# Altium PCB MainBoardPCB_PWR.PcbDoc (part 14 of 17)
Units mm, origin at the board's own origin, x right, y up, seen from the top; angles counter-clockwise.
Board outline 333.63 x 349.38 mm, 16 copper layers (L1, L2 (GND), L3 (Sign), L4 (GND), L5 (Sign), L6 (PWR/GND), L7(PWR/GND), L8 (PWR/GND), L9 (PWR/GND), L10 (PWR/GND), L11 (PWR/GND), L12 (Sign), L13 (GND), L14 (Sign), L15 (GND), L16), stack 2.503 mm thick; 2187 components, 1615 nets, 7987 pads, 1695 vias.
Unrouted connection lines stored in the file: 4757.
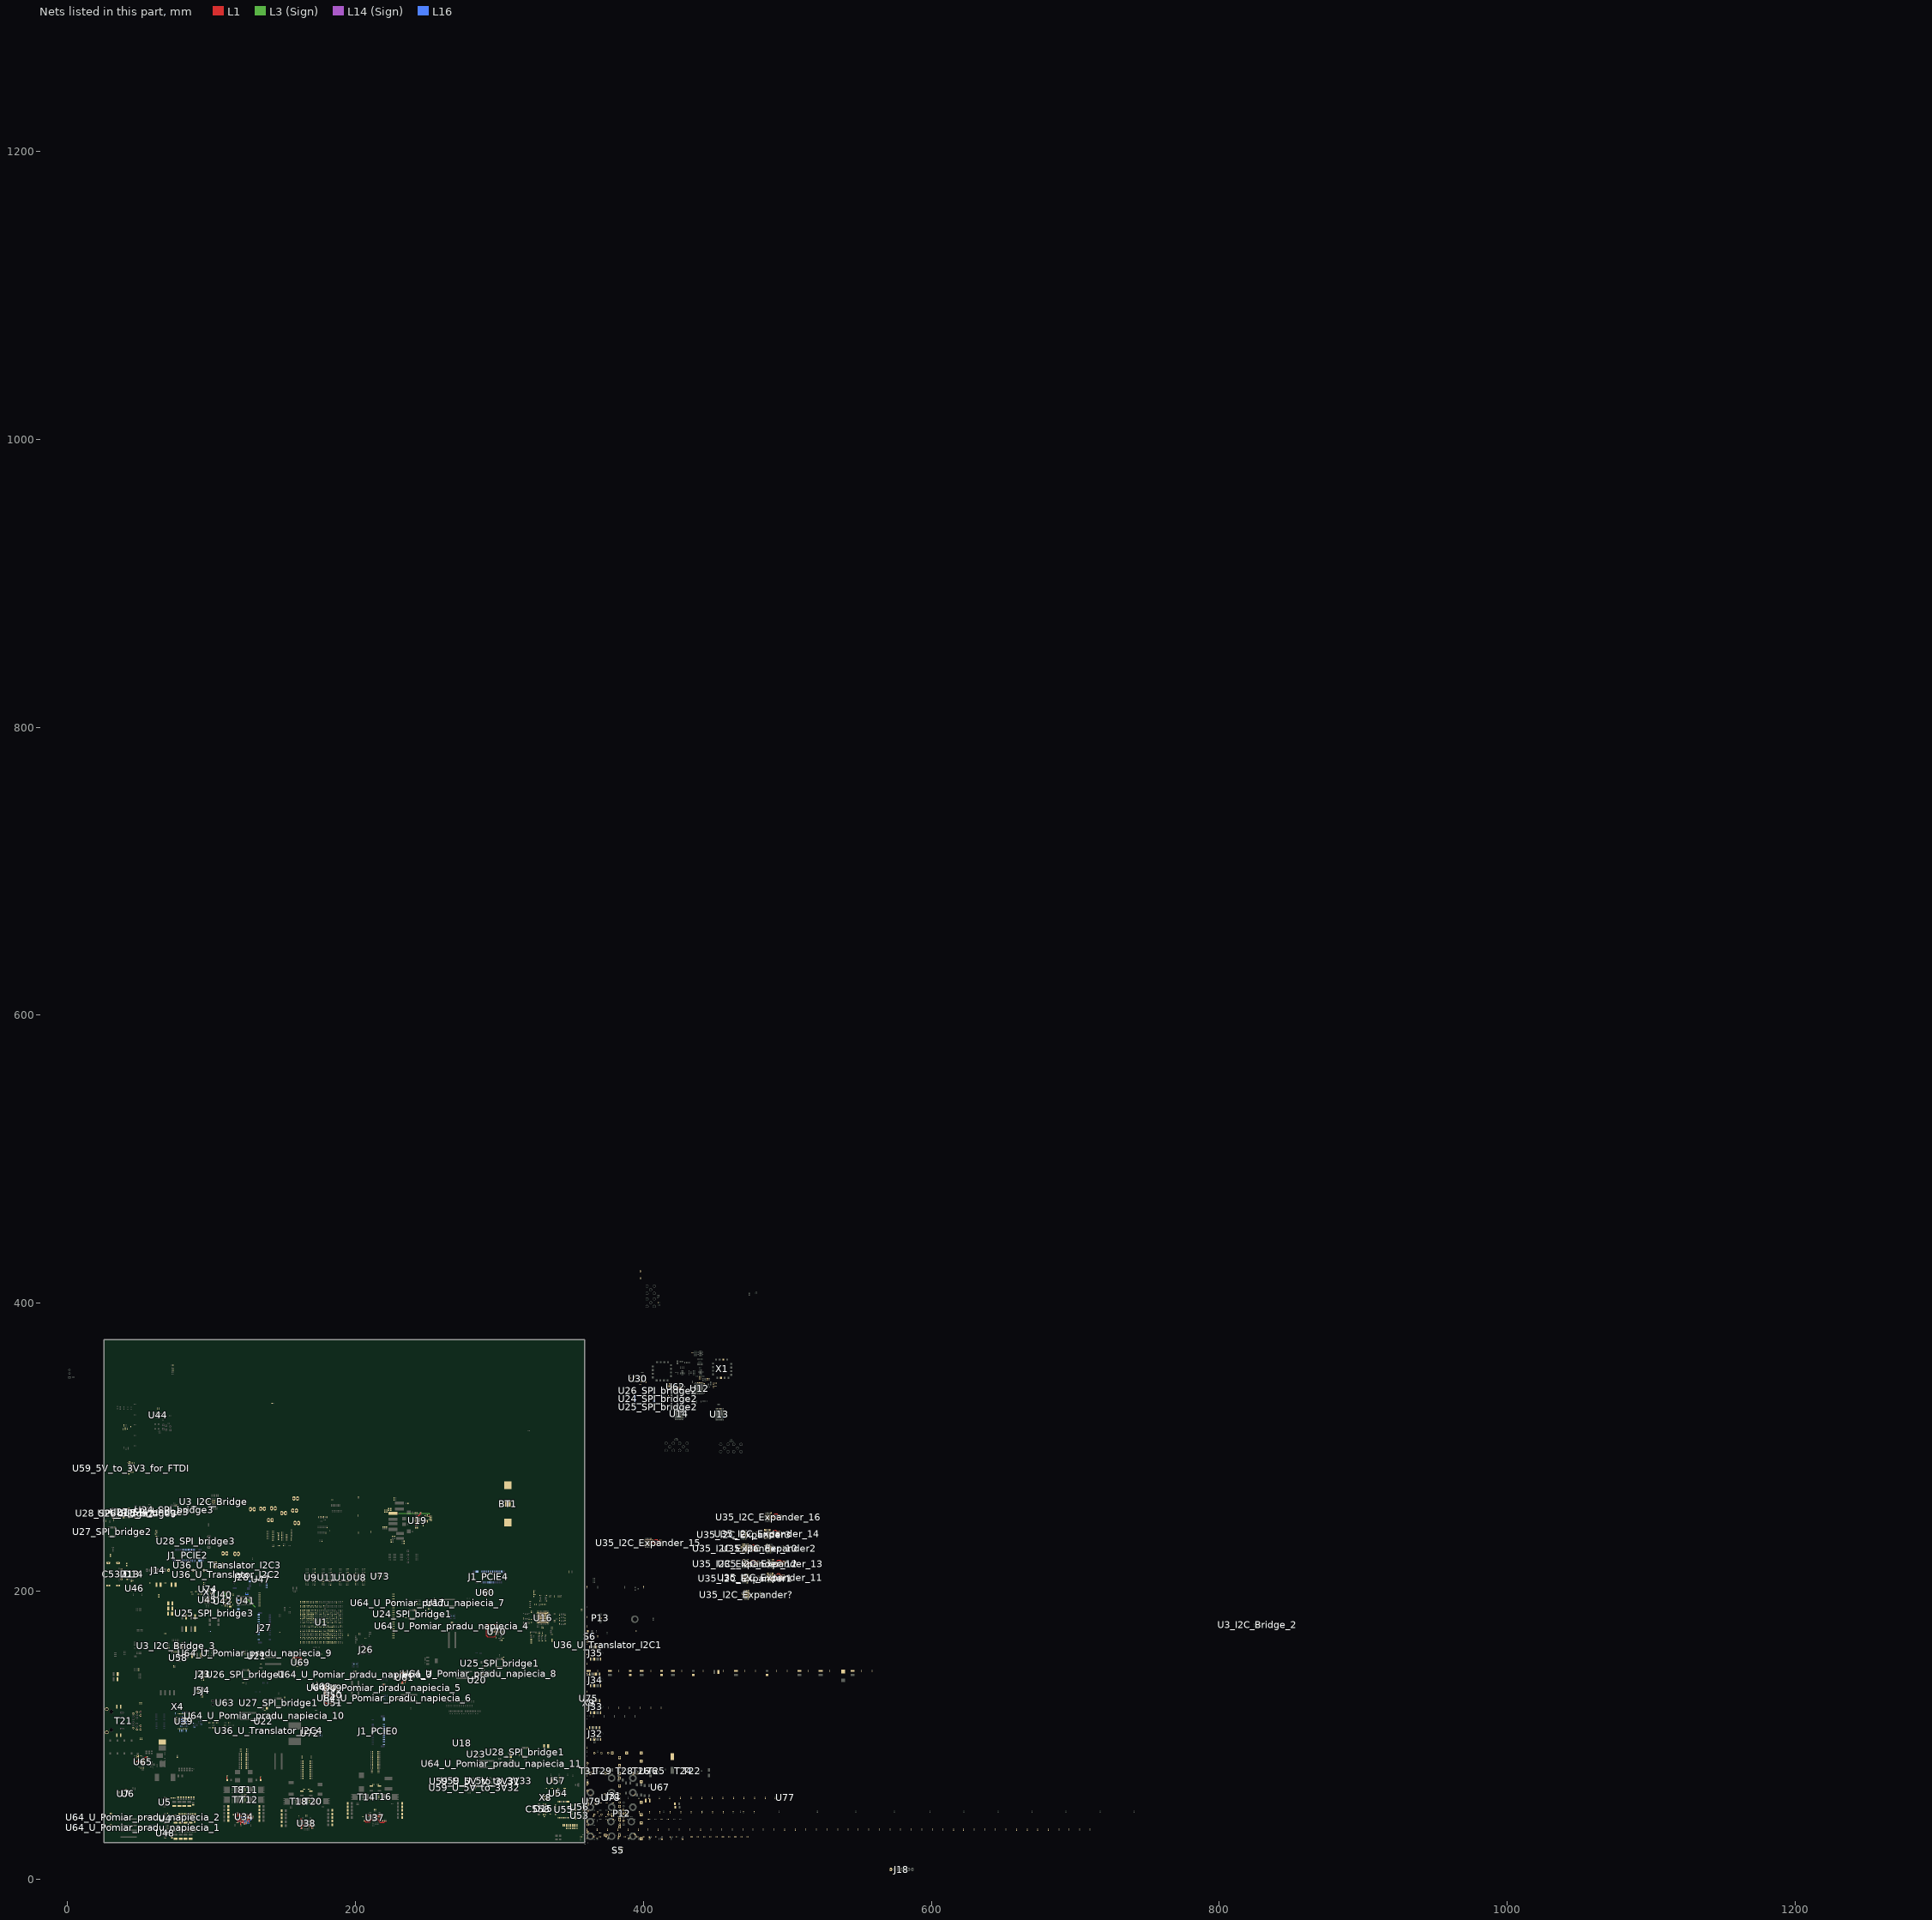
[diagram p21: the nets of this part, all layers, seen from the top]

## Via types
v1: diameter 0.5, hole 0.2, L1 to L16, 786 vias
v2: diameter 0.5/0.35/0.35/0.35/0.35/0.35/0.35/0.35/0.35/0.35/0.35/0.35/0.35/0.35/0.35/0.5 (per signal layer), hole 0.15, L1 to L16, tented both sides, 164 vias
v3: diameter 2.54, hole 1.02, L1 to L16, 152 vias
v4: diameter 0.5/0.35/0.35/0.35/0.35/0.35/0.35/0.35/0.35/0.35/0.35/0.35/0.35/0.35/0.35/0.5 (per signal layer), hole 0.2, L1 to L16, tented both sides, 100 vias
v5: diameter 0.45, hole 0.15, L1 to L16, 79 vias
v6: diameter 0.35/0/0.35 (per signal layer), hole 0.127, L1 to L3 (Sign), tented both sides, 78 vias
v7: diameter 0.45/0.45/0.45/0.45/0.45/0.45/0.45/0.45/0.45/0.45/0.45/0.45/0.45/0.45/0.45/0.45 (per signal layer), hole 0.15, L1 to L16, 65 vias
v8: diameter 0.4, hole 0.15, L1 to L16, 61 vias
v9: diameter 0.2, hole 0.1, L1 to L16, 35 vias
v10: diameter 0.5, hole 0.2, L1 to L16, tented both sides, 32 vias
v11: diameter 0.2/0/0.2 (per signal layer), hole 0.1, L1 to L3 (Sign), 28 vias
v12: diameter 0.4, hole 0.2, L1 to L16, 16 vias
v13: diameter 0.25, hole 0.2, L1 to L16, 16 vias
v14: diameter 0.3, hole 0.2, L1 to L16, 15 vias
v15: diameter 0.5/0.35/0.35/0.35/0.35/0.35/0.35/0.35/0.35/0.35/0.35/0.35/0.35/0.35/0.35/0.45 (per signal layer), hole 0.15, L1 to L16, tented both sides, 10 vias
v16: diameter 5, hole 3, L1 to L16, 9 vias
v17: diameter 0.2/0/0.2 (per signal layer), hole 0.1, L1 to L3 (Sign), tented both sides, 9 vias
v18: diameter 0.35/0/0.35 (per signal layer), hole 0.127, L1 to L3 (Sign), 7 vias
v19: diameter 0.35/0/0.35 (per signal layer), hole 0.127, L14 (Sign) to L16, tented both sides, 5 vias
v20: diameter 1.65, hole 1.65, L1 to L16, 4 vias
v21: diameter 1.15, hole 1.15, L1 to L16, 4 vias
v22: diameter 0.35, hole 0.127, L1 to L2 (GND), 2 vias
v23: diameter 0.4, hole 0.2, L1 to L16, tented both sides, 2 vias
v24: diameter 0.35, hole 0.127, L1 to L2 (GND), tented both sides, 2 vias
v25: diameter 0.508, hole 0.127, L1 to L2 (GND), 2 vias
v26: diameter 0.508, hole 0.127, L2 (GND) to L3 (Sign), 2 vias
v27: diameter 0.35, hole 0.127, L3 (Sign) to L6 (PWR/GND), tented both sides, 2 vias
v28: diameter 0.5, hole 0.2, L3 (Sign) to L6 (PWR/GND), tented both sides, 2 vias
v29: diameter 5.5, hole 3.5, L1 to L16, 1 vias
v30: diameter 0.45/0.45/0.45 (per signal layer), hole 0.15, L1 to L3 (Sign), 1 vias
v31: diameter 0.35/0.35/0.35 (per signal layer), hole 0.127, L1 to L3 (Sign), tented both sides, 1 vias
v32: diameter 0.45/0/0.45 (per signal layer), hole 0.15, L1 to L3 (Sign), tented both sides, 1 vias
v33: diameter 0.45/0/0.45 (per signal layer), hole 0.2, L14 (Sign) to L16, tented both sides, 1 vias
v34: diameter 0.35, hole 0.127, L2 (GND) to L3 (Sign), 1 vias

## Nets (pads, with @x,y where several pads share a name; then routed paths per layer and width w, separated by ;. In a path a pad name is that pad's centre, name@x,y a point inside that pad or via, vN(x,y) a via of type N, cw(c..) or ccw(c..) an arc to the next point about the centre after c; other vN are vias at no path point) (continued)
eMMC_GND: B1.2 BT1.1 C4.2 C5.2 C6.2 C7.2 C8.1 C9.1 C10.1 C11.1 C12.2 C13.2 C14.2 C15.2 C16.1 C17.1 C18.1 C19.1 C20.1 C21.1 C22.1 C23.1 C24.1 C25.1 C26.1 C27.1 C28.1 C29.1 C30.1 C31.1 C32.1 C33.1 C34.1 C35.1 C37.1 C38.2 C39.1 C40.2 C207.1 C208.2 C209.1 C210.2 C211.1 C212.2 C213.1 C214.2 C215.1 C216.2 C217.1 C218.2 C219.2 C220.2 C221.2 C222.2 C223.1 C224.1 C225.1 C226.1 C227.1 C228.1 C229.1 C230.1 C231.1 C232.1 C233.1 C234.1 C235.1 C236.1 C237.1 C238.1 C239.1 C240.1 C241.1 C242.1 C243.2 C244.2 C245.2 C246.2 C247.1 C248.1 C249.1 C250.1 C251.1 C252.1 C253.1 C254.1 C255.1 C256.1 C257.1 C258.1 C259.1 C260.1 C261.1 C262.1 C263.1 C264.1 C265.1 C266.1 C303_I2C_Bridge.1 C303_I2C_Bridge_2.1 C303_I2C_Bridge_3.1 C304.2 C305.2 C306.2 C307.2 C308.1 C309_U_Pomiar_pradu_napiecia_1.1 C309_U_Pomiar_pradu_napiecia_2.1 C309_U_Pomiar_pradu_napiecia_3.1 C309_U_Pomiar_pradu_napiecia_4.1 C309_U_Pomiar_pradu_napiecia_5.1 C309_U_Pomiar_pradu_napiecia_6.1 C309_U_Pomiar_pradu_napiecia_7.1 C309_U_Pomiar_pradu_napiecia_8.1 C309_U_Pomiar_pradu_napiecia_9.1 C309_U_Pomiar_pradu_napiecia_10.1 C309_U_Pomiar_pradu_napiecia_11.1 C310.1 C311_I2C_Expander1.1 C311_I2C_Expander2.1 C311_I2C_Expander3.1 C311_I2C_Expander?.1 C311_I2C_Expander_10.1 C311_I2C_Expander_11.1 C311_I2C_Expander_12.1 C311_I2C_Expander_13.1 C311_I2C_Expander_14.1 C311_I2C_Expander_15.1 C311_I2C_Expander_16.1 C331.1 C332.1 C347.1 C348.1 C352.1 C353.1 C354.1 C355.1 C358.1 C359.1 C360.1 C361.1 C362.1 C363.1 C364.1 C365.1 C366.1 C367.1 C368.1 C369.1 C370.1 C371.1 C372.1 C373.1 C374.1 C375.1 C376.1 C377.1 C378.1 C379.1 C380.1 C381.1 C382.1 C383.1 C384.1 C385.1 C386.1 C387.1 C388.1 C391.2 C392.1 C396.1 C397.2 C399.2 C400.1 C401.1 C402.1 C403.1 C404.1 C405.1 C406.1 C407.1 C408.1 C409.1 C410.1 C411.1 C412.1 C413.1 C414.1 C415.1 C416.1 C417.1 C418.1 C419.1 C420.1 C421.1 C422.1 C423.1 C424.1 C425.1 C426.1 C427.1 C428.1 C429.1 C432.2 C433.1 C437.1 C438.2 C440.2 C441.1 C442.1 C443.1 C444.1 C445.1 C446.1 C447.1 C448.1 C449.1 C450.1 C451.1 C452.1 C453.1 C454.1 C455.1 C456.1 C457.1 C458.1 C459.1 C460.1 C461.1 C462.1 C463.1 C464.1 C465.1 C466.1 C467.1 C468.1 C469.1 C470.1 C471.1 C472.1 C473.1 C474.1 C475.1 C476.1 C480.1 C481.1 C485.1 C486.1 C487.1 C488.1 C489.1 C490.1 C491.1 C492.1 C493.1 C494.1 C495.1 C496.1 C497.1 C498.1 C499.1 C500.1 C501.1 C502.1 C503.1 C504.1 C505.1 C506.1 C507.1 C508.1 C509.1 C510.1 C511.1 C512.1 C513.1 C514.1 C515.1 C516.1 C517.1 C518.1 C519.1 C520.1 C521.1 C522.1 C523.1 C524.1 C537.7 C538.1 C539.1 C544.1 C545.1 C546.1 C547.1 C550.1 C551.1 C552.1 C553.1 C554.1 C555.1 C561.1 C562.1 C585.1 C586.1 C587.1 C606.1 C607.1 C609.1 C610.1 C611.1 C613.1 C614.1 C615.1 C617.1 C618.1 C619.1 C620.1 C621.1 C622.1 C623.1 C624.1 C625.1 C626.1 C631.1 C632.1 C633.1 C636.1 C637.1 C638.1 C645.1 C646.1 C654.1 C655.2 C656.2 C657.2 C672.1 C674.1 C675.1 C676.1 C678.1 C679.1 C680.1 C705.1 C707.1 C708.1 C709.1 C711.1 C712.1 C719.1 C720.1 C721.1 C722.1 C723.1 C728.1 C729.1 C730.1 C731.1 C732.1 C733.1 C734.1 C735.1 C736.1 C737.1 C738.2 C739.2 C740.1 C741.1 C742.2 C743.1 C744.1 C745.1 C746.1 C747.2 C748.1 C749.1 C750.1 C751.2 C752.1 C753.2 C754.1 C755.1 C756.1 C757.2 C758.1 C759.1 C760.2 C761.1 C762.2 C763.1 C764.2 C765.1 C766.2 C767.2 C768.2 C769.2 C770.1 C771.1 C772.1 C773.1 C774.1 C775.1 C776.1 C777.1 C778.1 C779.1 C780.1 C781.1 C782.1 C783.1 C784.1 C785.1 C786.1 C787.1 C788.1 C789.1 C792.1 D13.3 D14.3 D14.8 D15.3 FB27.1 FB28.2 FB29.1 FB35.1 FB36.1 FB39.1 FB41.1 J14.1 J15.1 J16.1 J17.1 J18.1 J19.1 J20.1 J21.1 J22.1 J23.1 J24.1 J27.1 J27.3 J27.9 J27.15 J27.21 J27.27 J27.33 J27.39 J27.45 J27.51 J27.57 J27.63 J27.65 J27.67 J28.6 J31.SH1 J31.SH2 J31.SH3 J31.SH4 J31.SH5 J31.SH6 J31.SH7 J31.SH8 J31.SH9 J31.SH10 J31.SH11 J31.SH12 J31.SH13 J31.SH14 J31.SH15 J31.SH16 J31.SH17 J31.SH18 J31.SH19 J31.SH20 J31.SH21 J31.SH22 J31.SH23 J31.SH24 J31.SH25 J31.SH26 J31.SH27 J31.SH28 J31.SH29 J31.SH30 J31.SH31 J31.SH32 J31.SH33 J31.SH34 J31.SH35 J31.SH36 J31.SH37 J31.SH38 J31.SH39 J31.SH40 J31.SH41 J31.SH42 J31.SH43 J31.SH44 J31.SH45 J31.SH46 J32.1 J32.10 J32.11 J32.14 J32.17 J32.20 J33.1 J33.10 J33.11 J33.14 J33.16 J34.1 J34.10 J34.11 J34.14 J34.16 J35.1 J35.10 J35.11 J35.14 J35.16 P7.1 P9.1 P11.2 P12.2 P12.4 P12.6 P12.8 P12.10 P12.12 P12.14 R2.1 R14.1 R18.1 R19.1 R21.1 R23.1 R25.1 R26.1 R27.1 R28.1 R56.2 R60.2 R61.2 R62.2 R63.2 R64.2 R73.1 R74.1 R109.1 R114.1 R129.2 R139.1 R167.2 R168.2 R170.2 R172.2 R173.2 R174.1 R178.1 R182.1 R183.1 R187.1 R191.1 R192.1 R196.1 R200.1 R201.1 R205.1 R209.1 R210.1 R214.1 R217.1 R218.1 R228.1 R229.1 R242.2 R244.2 R267.1 R269.1 R274.1 R275.1 R279.2 R280.1 R282.2 R284.1 R292.1 R299.1 R304.1 R317.1 R325.1 R326.1 R327.1 R328.1 R334.2 R341.1 R344.1 R345.1 R379.1 R380.1 R393.1 R396.1 R399.1 R400.2 R450.2 R452.2 R454.2 R456.2 R460.2 R461.1 R464.2 R467.1 R470.2 R472.2 R474.2 R476.2 R478.2 R480.2 R493.2 R495.2 R497.2 R501.2 R503.2 R505.2 R509.2 R511.2 R513.2 R517.2 R519.2 R521.2 R525.2 R527.2 R529.2 R561.1 R565.1 R569.1 R573.1 R577.1 R581.1 R585.1 R589.1 R595.1 R601.1 R629.1 R645.1 R652.1 R668.1 R672.1 R674.1 R675.1 R681.1 R682.1 R683.1 R684.1 R685.1 R690.1 R693.2 R696.2 R698.2 R700.2 R702.2 R704.2 R706.2 R708.2 R714.1 R739.2 R741.2 R743.2 R759.2 R761.2 R763.2 R764.1 R838.2 R840.2 R841.2 S6.1 S6.2 T7.1 T7.2 T7.3 T8.1 T8.2 T8.3 T11.1 T11.2 T11.3 T12.1 T12.2 T12.3 T14.1 T14.2 T14.3 T16.1 T16.2 T16.3 T18.1 T18.2 T18.3 T20.1 T20.2 T20.3 T24.2 T25.2 T26.2 T28.2 T29.2 T31.2 U1.A1 U1.A2 U1.A5 U1.A9 U1.A11 U1.A30 U1.AA9 U1.AA19 U1.AA29 U1.AB2 U1.AB7 U1.AB12 U1.AB17 U1.AB22 U1.AC5 U1.AC10 U1.AC20 U1.AD13 U1.AD18 U1.AD23 U1.AE6 U1.AE16 U1.AE21 U1.AF4 U1.AF9 U1.AF19 U1.AF24 U1.AF29 U1.AG2 U1.AG12 U1.AG22 U1.AH5 U1.AH15 U1.AH20 U1.AH25 U1.AJ3 U1.AJ8 U1.AJ13 U1.AJ18 U1.AJ23 U1.AJ28 U1.AK1 U1.AK30 U1.B3 U1.B4 U1.B7 U1.B11 U1.B13 U1.B17 U1.C1 U1.C2 U1.C5 U1.C9 U1.C11 U1.C15 U1.C20 U1.C25 U1.C30 U1.D3 U1.D4 U1.D7 U1.D11 U1.E1 U1.E2 U1.E5 U1.E9 U1.E11 U1.F3 U1.F4 U1.F7 U1.F11 U1.F14 U1.F24 U1.F25 U1.F26 U1.F27 U1.F28 U1.F29 U1.F30 U1.G1 U1.G2 U1.G5 U1.G9 U1.G11 U1.G17 U1.G22 U1.G23 U1.G24 U1.G27 U1.G28 U1.H3 U1.H4 U1.H7 U1.H11 U1.H20 U1.H22 U1.H26 U1.H29 U1.H30 U1.J1 U1.J2 U1.J5 U1.J9 U1.J10 U1.J11 U1.J13 U1.J22 U1.J24 U1.J27 U1.J28 U1.K3 U1.K4 U1.K9 U1.K22 U1.K26 U1.K29 U1.K30 U1.L1 U1.L2 U1.L5 U1.L9 U1.L12 U1.L16 U1.L18 U1.L22 U1.L24 U1.L28 U1.M3 U1.M4 U1.M7 U1.M9 U1.M11 U1.M13 U1.M15 U1.M17 U1.M22 U1.M26 U1.M29 U1.M30 U1.N1 U1.N2 U1.N5 U1.N9 U1.N12 U1.N14 U1.N16 U1.N23 U1.N24 U1.N25 U1.N26 U1.N27 U1.N28 U1.N29 U1.N30 U1.P3 U1.P4 U1.P7 U1.P9 U1.P11 U1.P13 U1.P15 U1.P17 U1.R1 U1.R2 U1.R5 U1.R9 U1.R12 U1.R16 U1.R21 U1.R26 U1.T3 U1.T4 U1.T7 U1.T8 U1.T11 U1.T13 U1.T17 U1.T19 U1.T24 U1.T29 U1.U1 U1.U2 U1.U5 U1.U7 U1.U12 U1.U16 U1.U22 U1.U27 U1.V3 U1.V4 U1.V7 U1.V9 U1.V11 U1.V13 U1.V20 U1.V25 U1.W1 U1.W2 U1.W5 U1.W6 U1.W12 U1.W14 U1.W16 U1.W18 U1.W23 U1.W28 U1.Y2 U1.Y3 U1.Y4 U1.Y5 U1.Y11 U1.Y13 U1.Y15 U1.Y21 U1.Y26 U3_I2C_Bridge.9 U3_I2C_Bridge.25 U3_I2C_Bridge_2.9 U3_I2C_Bridge_2.25 U3_I2C_Bridge_3.9 U3_I2C_Bridge_3.25 U4.3 U4.6 U4.12 U5.3 U5.6 U5.12 U6.A1 U6.A4 U6.B1 U6.B2 U6.B3 U6.B4 U6.C4 U7.A1 U7.A4 U7.B1 U7.B2 U7.B3 U7.B4 U7.C4 U8.A2 U8.A5 U8.B2 U8.C6 U8.D2 U8.D5 U8.E1 U8.E3 U8.E5 U8.E6 U8.F1 U8.G5 U8.H1 U8.H6 U8.K1 U8.K6 U8.M6 U8.N1 U8.T1 U9.A2 U9.A5 U9.B2 U9.C6 U9.D2 U9.D5 U9.E1 U9.E3 U9.E5 U9.E6 U9.F1 U9.G5 U9.H1 U9.H6 U9.K1 U9.K6 U9.M6 U9.N1 U9.T1 U10.A2 U10.A5 U10.B2 U10.C6 U10.D2 U10.D5 U10.E1 U10.E3 U10.E5 U10.E6 U10.F1 U10.G5 U10.H1 U10.H6 U10.K1 U10.K6 U10.M6 U10.N1 U10.T1 U11.A2 U11.A5 U11.B2 U11.C6 U11.D2 U11.D5 U11.E1 U11.E3 U11.E5 U11.E6 U11.F1 U11.G5 U11.H1 U11.H6 U11.K1 U11.K6 U11.M6 U11.N1 U11.T1 U15.2 U15.10 U17.A1 U17.A4 U17.B1 U17.B2 U17.B3 U17.B4 U17.C4 U18.A1 U18.A4 U18.B1 U18.B2 U18.B3 U18.B4 U18.C4 U19.10 U19.18 U19.27 U19.29 U20.A1 U20.A4 U20.B1 U20.B2 U20.B3 U20.B4 U20.C4 U21.A1 U21.A4 U21.B1 U21.B2 U21.B3 U21.B4 U21.C4 U22.A1 U22.A4 U22.B1 U22.B2 U22.B3 U22.B4 U22.C4 U23.A1 U23.A4 U23.B1 U23.B2 U23.B3 U23.B4 U23.C4 U24_SPI_bridge1.2 U24_SPI_bridge1.10 U24_SPI_bridge2.2 U24_SPI_bridge2.10 U24_SPI_bridge3.2 U24_SPI_bridge3.10 U25_SPI_bridge1.2 U25_SPI_bridge1.10 U25_SPI_bridge2.2 U25_SPI_bridge2.10 U25_SPI_bridge3.2 U25_SPI_bridge3.10 U26_SPI_bridge1.2 U26_SPI_bridge1.10 U26_SPI_bridge2.2 U26_SPI_bridge2.10 U26_SPI_bridge3.2 U26_SPI_bridge3.10 U27_SPI_bridge1.2 U27_SPI_bridge1.10 U27_SPI_bridge2.2 U27_SPI_bridge2.10 U27_SPI_bridge3.2 U27_SPI_bridge3.10 U28_SPI_bridge1.2 U28_SPI_bridge1.10 U28_SPI_bridge2.2 U28_SPI_bridge2.10 U28_SPI_bridge3.2 U28_SPI_bridge3.10 U34.19 U34.22 U35_I2C_Expander1.6 U35_I2C_Expander1.29 U35_I2C_Expander2.6 U35_I2C_Expander2.29 U35_I2C_Expander3.6 U35_I2C_Expander3.29 U35_I2C_Expander?.6 U35_I2C_Expander?.29 U35_I2C_Expander_10.6 U35_I2C_Expander_10.29 U35_I2C_Expander_11.6 U35_I2C_Expander_11.29 U35_I2C_Expander_12.6 U35_I2C_Expander_12.29 U35_I2C_Expander_13.6 U35_I2C_Expander_13.29 U35_I2C_Expander_14.6 U35_I2C_Expander_14.29 U35_I2C_Expander_15.6 U35_I2C_Expander_15.29 U35_I2C_Expander_16.6 U35_I2C_Expander_16.29 U36_U_Translator_I2C1.1 U36_U_Translator_I2C2.1 U36_U_Translator_I2C3.1 U36_U_Translator_I2C4.1 U37.19 U37.22 U38.19 U38.22 U39.49 U40.4 U40.9 U41.A6 U41.C4 U41.E7 U41.G5 U41.H10 U41.J5 U41.K8 U41.N2 U41.N5 U41.P4 U41.P6 U42.4 U42.9 U45.23 U45.33 U46.A1 U46.A4 U46.B1 U46.B2 U46.B4 U47.C3 U48.12 U49.4 U49.9 U50.4 U50.9 U51.4 U51.9 U58.2 U58.3 U58.6 U58.7 U63.2 U63.8 U64_U_Pomiar_pradu_napiecia_1.7 U64_U_Pomiar_pradu_napiecia_2.7 U64_U_Pomiar_pradu_napiecia_3.7 U64_U_Pomiar_pradu_napiecia_4.7 U64_U_Pomiar_pradu_napiecia_5.7 U64_U_Pomiar_pradu_napiecia_6.7 U64_U_Pomiar_pradu_napiecia_7.7 U64_U_Pomiar_pradu_napiecia_8.7 U64_U_Pomiar_pradu_napiecia_9.7 U64_U_Pomiar_pradu_napiecia_10.7 U64_U_Pomiar_pradu_napiecia_11.7 U67.2 U68.2 U69.6 U69.17 U70.3 U70.8 U70.13 U70.18 U70.21 U72.7 U73.4 U73.9 U74.3 U75.3 U78.2 X4.2 X4.4 X7.2 X7.4 | length 5.7
  L1 w0.254: U1.AF24@186.927,186.927 v24(186.931,186.923) ; v24(187.924,184.927) U1.AG22@187.927,184.927 ; v22(242.224,246.141) U19.10@242.224,246.658 ; U19.27@242.224,251.458 v18(242.224,252.049) ; v8(295.595,171.723) U70.3@296.284,171.723 v1(297.359,171.723) v1(298.259,171.723)
  L16 w0.254: R577.1@219.302,140.072 R581.1@221.208,140.072
  other v1: 80.087,107.674 81.457,107.674 78.972,108.789 80.087,108.789 81.457,108.789 82.572,108.789 78.972,110.159 80.087,110.159 81.457,110.159 82.572,110.159 80.087,111.274 81.457,111.274 183.759,122.038 184.759,122.038 183.759,123.038 184.759,123.038 183.759,127.285 184.759,127.285 183.759,128.285 184.759,128.285 183.759,132.134 184.759,132.134 183.759,133.134 184.759,133.134 161.168,149.912 162.268,149.912 161.168,151.012 162.268,151.012 297.359,170.823 298.259,170.823 299.159,170.823 299.159,171.723 297.359,172.623 298.259,172.623 299.159,172.623 107.317,192.548 108.317,192.548 107.317,193.548 108.317,193.548 107.316,196.835 108.316,196.835 107.316,197.835 108.316,197.835 469.236,207.067 470.336,207.067 471.436,207.067 472.536,207.067 469.236,208.167 470.336,208.167 471.436,208.167 472.536,208.167 469.236,209.267 470.336,209.267 471.436,209.267 472.536,209.267 216.651,209.883 217.651,209.883 469.236,210.367 470.336,210.367 471.436,210.367 472.536,210.367 216.651,210.883 217.651,210.883 469.12,217.4 470.22,217.4 471.32,217.4 472.42,217.4 469.12,218.5 470.22,218.5 471.32,218.5 472.42,218.5 469.12,219.6 470.22,219.6 471.32,219.6 472.42,219.6 469.12,220.7 470.22,220.7 471.32,220.7 472.42,220.7 485.515,227.915 486.615,227.915 487.715,227.915 488.815,227.915 485.515,229.015 486.615,229.015 487.715,229.015 488.815,229.015 485.515,230.115 486.615,230.115 487.715,230.115 488.815,230.115 485.515,231.215 486.615,231.215 487.715,231.215 488.815,231.215 401.804,231.87 402.904,231.87 404.004,231.87 405.104,231.87 401.804,232.97 402.904,232.97 404.004,232.97 405.104,232.97 401.804,234.07 402.904,234.07 404.004,234.07 405.104,234.07 401.804,235.17 402.904,235.17 404.004,235.17 405.104,235.17 468.195,237.62 469.295,237.62 470.395,237.62 471.495,237.62 468.195,238.72 469.295,238.72 470.395,238.72 471.495,238.72 468.195,239.82 469.295,239.82 470.395,239.82 471.495,239.82 468.195,240.92 469.295,240.92 470.395,240.92 471.495,240.92 242.424,247.958 243.524,247.958 242.424,249.058 243.524,249.058 485.203,249.839 486.303,249.839 487.403,249.839 488.503,249.839 242.424,250.158 243.524,250.158 485.203,250.939 486.303,250.939 487.403,250.939 488.503,250.939 485.203,252.039 486.303,252.039 487.403,252.039 488.503,252.039 485.203,253.139 486.303,253.139 487.403,253.139 488.503,253.139
  other v4: 220.255,140.072 181.927,191.927
  other v5: 66.285,34.081 69.809,35.032 66.285,36.958 69.753,37.017 67.96,38.575 67.56,45.343 67.854,50.161 69.587,56.524 67.512,56.624 292.356,170.033 294.076,170.033
  other v10: 178.927,187.927 180.927,188.927 179.927,190.927
  other v13: 95.498,192.272 96.518,192.272 97.538,192.272 98.558,192.272 95.498,193.292 96.518,193.292 97.538,193.292 98.558,193.292 95.498,194.312 96.518,194.312 97.538,194.312 98.558,194.312 95.498,195.332 96.518,195.332 97.538,195.332 98.558,195.332
  other v14: 75.299,161.107 74.454,161.955 75.299,161.955 76.124,161.955 75.299,162.805 826.389,175.733 825.544,176.581 826.389,176.581 827.214,176.581 826.389,177.431 101.6,261.154 100.755,262.001 101.6,262.001 102.425,262.001 101.6,262.851
eMMC_PG1: R340.1 U40.5 | length 3.6
  L1 w0.164: U40.5@109.116,196.323 U40.5@109.116,196.36 ; v18(109.726,199.669) R340.1@109.776,199.669
  L3 (Sign) w0.164: v18(109.416,196.36) 109.452,196.396 109.665,196.396 109.726,196.456 v18(109.726,199.669)
eMMC_PG2: R343.1 R345.2 U42.5 | length 3.1
  L1 w0.164: U42.5@109.117,192.073 109.242,192.073 109.335,191.98 109.335,191.855 109.572,191.618 R345.2@109.572,190.652 ; R345.2@109.572,190.636 R345.2@109.572,190.652 ; R343.1@110.957,190.652 R345.2@109.572,190.652
eMMC_rst: R99.1 R797.1 U41.K5 | length 10.4
  L1 w0.254: U41.K5@122.468,194.479 v17(122.479,194.479)
  L3 (Sign) w0.098: v17(122.479,194.479) 122.729,194.729 124.47,194.729 130.169,189.031 130.362,189.031
eMMC_Vcc: C517.2 C518.2 C523.2 C586.2 FB25.1 R339.2 R340.2 U40.8 U41.E6 U41.F5 U41.J10 U41.K9
  other v1: 118.164,196.899 119.264,196.899
eMMC_VccQ: C519.2 C520.2 C524.2 C587.2 FB25.2 R342.2 R343.2 U41.C6 U41.M4 U41.N4 U41.P3 U41.P5 U42.8
  other v1: 111.29,188.882 118.249,190.694 119.22,190.694 111.357,193.452 111.357,194.212
eMMC_Vddim: C521.2 C522.2 U41.C2 | length 1.6
  L16 w0.164: C522.2@123.76,197.623 C521.2@125.318,197.623
EN1: U35_I2C_Expander2.23 U61.20
EN1_TPS: R277.2 R278.2 U34.14 U34.27 U70.20 | length 8.3
  L1 w0.254: R278.2@116.439,43.474 116.439,43.524 116.612,43.697 117.019,43.697 117.228,43.906 U34.27@120.477,43.906 ; U34.14@124.977,43.906 124.979,43.904 125.128,43.904 125.132,43.899 126.383,43.899 126.903,43.379 128.704,43.379 R277.2@128.799,43.474
EN2: U35_I2C_Expander2.24 U61.6
EN2_TPS: R745.1 U70.6 U70.17 | length 25
  L1 w0.254: U70.6@297.259,169.748 297.259,168.891 296.591,168.223 291.986,168.223 291.068,169.141 291.068,175.325 292.548,176.805 R745.1@298.259,176.805 298.409,176.655 298.409,176.07 298.399,176.06 298.399,174.709 298.759,174.349 U70.17@298.759,173.698
EN_0.85V_REG1: S5.8 U34.1 U34.8
En_0V85@2A: R296.2 R435.2 U37.14 | length 1.3
  L1 w0.254: U37.14@215.795,43.359 R296.2@217.105,43.359
EN_1V0@1.5A: R634.1 U51.3 U68.4 | length 14.8
  L1 w0.254: U68.4@178.016,132.909 178.266,132.909 178.743,132.432 178.743,123.104 179.628,122.219 R634.1@180.597,122.219 180.6,122.216 182.956,122.216 U51.3@182.959,122.213
EN_1V8@1.5A: R633.1 U50.3 U68.5 | length 10.9
  L1 w0.254: U68.5@178.016,133.859 179.114,133.859 179.263,133.711 179.263,128.084 179.887,127.46 180.564,127.46 R633.1@180.597,127.428 180.613,127.444 182.943,127.444 U50.3@182.959,127.46
EN_2V5@1.5A: R632.1 U49.3 U68.6 | length 6.8
  L1 w0.254: U68.6@178.016,134.809 179.003,134.809 179.803,134.009 179.803,132.644 180.069,132.378 180.424,132.378 R632.1@180.547,132.255 180.601,132.309 U49.3@182.959,132.309
EN_3V3V_REG0: S5.6 U37.1
EN_5V_REG0: S5.7 U38.8
EN_12@8A: S5.5 U38.1
EN_Detect_KEY: R655.2
En_PCIE_I2C: U35_I2C_Expander_14.21
En_PCIE_SPI: U35_I2C_Expander_14.20
EN_PS_LTC6952_1: U35_I2C_Expander2.20 U59_U_5V_to_3V33.3
EN_PS_LTC6952_2: U35_I2C_Expander2.22 U59_U_5V_to_3V32.3
EN_PS_LTC6952_3: U35_I2C_Expander2.17 U59_U_5V_to_3V31.3
En_PWRSwitch_PCIE0: U17.A2 U35_I2C_Expander_14.2
En_PWRSwitch_PCIE1: U20.A2 U35_I2C_Expander_14.18
En_PWRSwitch_PCIE2: U21.A2 U35_I2C_Expander_14.3
En_PWRSwitch_PCIE3: U22.A2 U35_I2C_Expander_14.22
En_PWRSwitch_PCIE4: U23.A2 U35_I2C_Expander_14.19
  other v1: 484.417,237.997 485.517,237.997 486.617,237.997 487.717,237.997 484.417,239.097 485.517,239.097 486.617,239.097 487.717,239.097 484.417,240.197 485.517,240.197 486.617,240.197 487.717,240.197 484.417,241.297 485.517,241.297 486.617,241.297 487.717,241.297
EN_SEQ_LT3504: R646.2 U67.3 U69.5 | length 8.3
  L1 w0.254: R646.2@156.588,153.062 156.588,153.809 156.781,154.002 161.918,154.002 162.693,153.227 U69.5@162.693,152.137
EN_SPI_A_Q0: R232_SPI_bridge3.1 U35_I2C_Expander_10.21
EN_SPI_A_Q1: R234_SPI_bridge3.1 U35_I2C_Expander_10.20
EN_SPI_A_Q2: R235_SPI_bridge3.2 U35_I2C_Expander_10.2
EN_SPI_A_Q3: R237_SPI_bridge3.2 U35_I2C_Expander_10.18
EN_SPI_A_Q4: R239_SPI_bridge3.1 U35_I2C_Expander_10.3
EN_SPI_B_Q0: R232_SPI_bridge1.1 U35_I2C_Expander_10.22 U35_I2C_Expander_15.1
EN_SPI_B_Q1: R234_SPI_bridge1.1 U35_I2C_Expander_10.19 U35_I2C_Expander_15.28
EN_SPI_B_Q2: R235_SPI_bridge1.2 U35_I2C_Expander_10.17 U35_I2C_Expander_15.25
EN_SPI_B_Q3: R237_SPI_bridge1.2 U35_I2C_Expander_10.4 U35_I2C_Expander_15.26
EN_SPI_B_Q4: R239_SPI_bridge1.1 U35_I2C_Expander_10.23 U35_I2C_Expander_15.27
EN_SPI_C_Q0: R232_SPI_bridge2.1 U35_I2C_Expander_10.24
EN_SPI_C_Q1: R234_SPI_bridge2.1 U35_I2C_Expander_10.1
EN_SPI_C_Q2: R235_SPI_bridge2.2 U35_I2C_Expander_10.28
EN_SPI_C_Q3: R237_SPI_bridge2.2 U35_I2C_Expander_10.25
EN_SPI_C_Q4: R239_SPI_bridge2.1 U35_I2C_Expander_10.26
EN_VSUP_1V2: C626.2 R309.1 U19.12
EN_VSUP_1V8: C625.2 R308.1 U19.15
EN_VSUP_3V3: C624.2 R305.1 U19.14
Enable_CLK: U12.40 U13.40 U14.40 U35_I2C_Expander?.25
EXPANDER_RESET: J21.2 P13.2 R811.1 U35_I2C_Expander?.14
Ext_EZS_N: R82.1 U1.AK6 U12.48
Ext_EZS_P: R82.2 U1.AK7 U12.47
FB1/FB2: R271.1 R273.2 U34.10 U34.31 | length 12.3
  L1 w0.254: R271.1@118.246,39.126 118.296,39.126 v1(118.696,39.526) ; R273.2@118.596,41.023 118.713,40.906 v1(119.896,40.906) 119.887,40.915 119.887,41.656 120.135,41.904 120.475,41.904 U34.31@120.477,41.906 ; U34.10@124.977,41.906 124.979,41.904 125.476,41.904 125.752,41.628 v1(125.752,40.904)
  L16 w0.254: v1(118.596,40.898) 118.596,40.859 118.696,40.759 v1(118.696,39.526) ; v1(125.752,40.904) 125.751,40.905 v1@119.897,40.905 ; v1(119.896,40.906) v1@119.897,40.905
FB1_1: R287.1 R290.2 U37.31 | length 7.1
  L1 w0.254: R287.1@205.838,40.414 R290.2@206.788,40.414 206.866,40.336 206.866,39.9 207.015,39.751 210.164,39.751 210.623,40.21 210.623,41.009 210.973,41.359 U37.31@211.295,41.359
FB1_2: R626.1 R627.2 U38.31 | length 3.3
  L1 w0.254: R626.1@162.787,35.058 162.775,35.07 162.775,35.994 R627.2@162.764,36.005 162.922,36.164 162.922,37.314 163.123,37.515 U38.31@163.783,37.515
FB2_1: R297.1 R300.2 U37.10 | length 7.6
  L1 w0.254: U37.10@215.795,41.359 216.376,41.359 216.54,41.196 216.54,39.949 217.073,39.416 219.835,39.416 220.17,39.751 R300.2@220.17,40.315 R297.1@221.201,40.315
FB2_2: R315.1 R318.2 U38.10 | length 3.5
  L1 w0.254: U38.10@168.283,37.515 168.833,37.515 169.006,37.342 169.006,36.445 169.349,36.103 R315.1@169.774,36.103 R318.2@169.774,35.175
Flag_PWRSwitch_PCIE0: R602.2 U17.A3 U35_I2C_Expander_14.4
Flag_PWRSwitch_PCIE1: R603.2 U20.A3 U35_I2C_Expander_14.23
Flag_PWRSwitch_PCIE2: R604.2 U21.A3 U35_I2C_Expander_14.24
Flag_PWRSwitch_PCIE3: R605.2 U22.A3 U35_I2C_Expander_14.1
Flag_PWRSwitch_PCIE4: R606.2 U23.A3 U35_I2C_Expander_14.28
FPGA_Vcc_HD: C605.2 C606.2 C607.2 C610.2 C611.2 C756.2 C759.2 L16.2 R212.2 R365.1 R395.2 R398.2 R618.2 R659.2 R660.2 R661.2 R662.2 R663.2 R664.2 R688.2 R744.2 R817.2 R818.2 R819.2 R820.2 R821.2 R822.2 R823.2 R824.2 U1.AA4 U1.AC15 U1.AD3 U1.AD8 U1.AE11 U1.AF14 U1.AG7 U1.AG17 U1.AH10 U1.D13 U1.E10 U1.E16 U1.G10 U1.G12 U1.H15 U1.H25 U1.K25 U1.L27 U15.1 U15.7 U15.8 U15.16 U36_U_Translator_I2C1.2 U36_U_Translator_I2C4.2 U79.15 | length 27.3
  L1 w0.254: L16.2@225.965,254.051 225.981,254.066 v18(229.614,254.066) ; R212.2@251.788,252.024 v18(251.788,253.026)
  L3 (Sign) w0.254: v18(229.614,254.066) 250.748,254.066 v18(251.788,253.026)
FPGA_Vcc_HP: R363.1 R364.1 R506.1 R507.1 R514.1 R515.1 R522.1 R523.1 R530.1 R531.1 R546.1 R547.1 R548.1 R549.1 R550.1 R551.1 R552.1 R553.1 R554.1 R555.1 R556.1 R557.1 R735.1
FTD_DS_Dir1: R411.2 R412.2 U56.1
FTD_DS_Dir2: R413.2 R414.2 U56.2
FTD_DS_Dir3: R415.2 R416.2 U56.7
FTD_DS_Dir4: R418.2 R421.2 U56.8
FTD_JTAG_Dir1: R402.2 R403.2 U53.1
FTD_JTAG_Dir2: R404.2 R405.2 U53.2
FTD_JTAG_Dir3: R406.2 R407.2 U53.7
FTD_JTAG_Dir4: R408.2 R409.2 U53.8
FTD_U1_DIR1: R722.2 R723.2 U79.1
FTD_U1_DIR2: R724.2 R725.2 U79.2
FTD_U1_DIR3: R726.2 R727.2 U79.7
FTD_U1_DIR4: R728.2 R729.2 U79.8
FTD_U_DIR1: R636.2 R637.2 U57.1
FTD_U_DIR2: R638.2 R639.2 U57.2
FTD_U_DIR3: R640.2 R641.2 U57.7
FTD_U_DIR4: R642.2 R643.2 U57.8
FTDI_5V: C559.2 C560.2 C563_5V_to_3V3_for_FTDI.2 C564_5V_to_3V3_for_FTDI.2 FB31.1 U59_5V_to_3V3_for_FTDI.1 U59_5V_to_3V3_for_FTDI.2 U59_5V_to_3V3_for_FTDI.3
FTDI_DM: C558.2 D15.2 U55.7
FTDI_DP: C558.3 D15.1 U55.8
FTDI_EECLK: R417.2 U54.4 U55.62
FTDI_EECS: R420.2 U54.5 U55.63
FTDI_EED: R419.1 U54.3 U55.61
FTDI_GND: C559.1 C560.1 C563_5V_to_3V3_for_FTDI.1 C564_5V_to_3V3_for_FTDI.1 C565_5V_to_3V3_for_FTDI.1 C566_5V_to_3V3_for_FTDI.1 C567_5V_to_3V3_for_FTDI.1 C658.1 C659.1 C660.1 C661.1 C662.1 C663.1 C664.1 C665.1 C666.1 C667.1 C668.1 C669.1 C670.1 C671.1 C673.1 C791.1 FB32.1 R403.1 R405.1 R407.1 R409.1 R412.1 R414.1 R416.1 R421.1 R423.1 R432_5V_to_3V3_for_FTDI.1 R637.1 R639.1 R641.1 R643.1 R723.1 R725.1 R727.1 R729.1 U53.10 U54.2 U55.1 U55.5 U55.10 U55.11 U55.13 U55.15 U55.25 U55.35 U55.47 U55.51 U56.10 U57.10 U59_5V_to_3V3_for_FTDI.4 U59_5V_to_3V3_for_FTDI.9 U77.2 U79.10 X8.2 X8.4
  other v1: 43.576,284.84 44.576,284.84 43.576,285.84 44.576,285.84
  other v5: 44.222,289.442 41.72,289.909
FTDI_JTAG_ON: U55.21
FTDI_JTAG_ON_1: R401.1 U53.9
FTDI_JTAG_ON_2: R410.1 U56.9
FTDI_JTAG_ON_3: R635.1 U57.9
FTDI_JTAG_ON_4: R721.1 U79.9
FTDI_LS_UART0_RXD: U55.27 U79.4
FTDI_LS_UART0_TXD: U55.26 U79.3
FTDI_LS_UART2_CTS_B: U55.41
FTDI_LS_UART2_RTS_B: U55.40
FTDI_LS_UART2_RXD: U55.39 U57.6
FTDI_LS_UART2_TXD: U55.38 U57.5
FTDI_LS_UART_RXD: U55.52 U57.4
FTDI_LS_UART_TXD: U55.48 U57.3
FTDI_PS_POR: U55.23 U77.1
FTDI_PS_SRST+B: U55.24 U77.3
FTDI_Sock_GND: C558.5 FB32.2
FTDI_TCK: P12.5 R732.1 U53.5 U55.16 U56.5
FTDI_TDI: P12.9 R734.1 U53.3 U55.17 U56.3
FTDI_TDO: P12.7 R733.1 U53.6 U55.18 U56.6
FTDI_TMS: P12.3 R731.1 U53.4 U55.19 U56.4
FTDI_VBUS: C558.1 FB31.2
FTDI_VCC1P8: C665.2 C666.2 C667.2 C673.2 U55.12 U55.37 U55.49 U55.64
FTDI_VccIO: C565_5V_to_3V3_for_FTDI.2 C566_5V_to_3V3_for_FTDI.2 C567_5V_to_3V3_for_FTDI.2 C658.2 C668.2 C669.2 C670.2 C671.2 C791.2 FB43.1 FB44.1 R401.2 R402.1 R404.1 R406.1 R408.1 R410.2 R411.1 R413.1 R415.1 R417.1 R418.1 R420.1 R422.2 R424.1 R430_5V_to_3V3_for_FTDI.2 R431_5V_to_3V3_for_FTDI.2 R635.2 R636.1 R638.1 R640.1 R642.1 R721.2 R722.1 R724.1 R726.1 R728.1 U53.16 U54.6 U55.20 U55.31 U55.42 U55.50 U55.56 U56.16 U57.16 U59_5V_to_3V3_for_FTDI.8 U77.5 U79.16
FTDI_X_IN: C663.2 U55.2 X8.1
FTDI_X_OUT: C664.2 U55.3 X8.3
GEM3_MDC: R815.1 U39.16
GEM3_MDIO: R333.2 R816.1 U39.17
GND_PCIe_PCIE0: C1_PCIE0.1 C2_PCIE0.1 C3_PCIE0.1 J1_PCIE0.1 J1_PCIE0.3 J1_PCIE0.9 J1_PCIE0.15 J1_PCIE0.21 J1_PCIE0.24 J1_PCIE0.27 J1_PCIE0.30 J1_PCIE0.33 J1_PCIE0.34 J1_PCIE0.38 J1_PCIE0.39 J1_PCIE0.42 J1_PCIE0.45 J1_PCIE0.48 J1_PCIE0.51 J1_PCIE0.54 J1_PCIE0.57 J1_PCIE0.59 J1_PCIE0.61 J1_PCIE0.63 J1_PCIE0.65 J1_PCIE0.67
GND_PCIe_PCIE1: C1_PCIE1.1 C2_PCIE1.1 C3_PCIE1.1
GND_PCIe_PCIE2: C1_PCIE2.1 C2_PCIE2.1 C3_PCIE2.1 J1_PCIE2.1 J1_PCIE2.3 J1_PCIE2.9 J1_PCIE2.15 J1_PCIE2.21 J1_PCIE2.24 J1_PCIE2.27 J1_PCIE2.30 J1_PCIE2.33 J1_PCIE2.34 J1_PCIE2.38 J1_PCIE2.39 J1_PCIE2.42 J1_PCIE2.45 J1_PCIE2.48 J1_PCIE2.51 J1_PCIE2.54 J1_PCIE2.57 J1_PCIE2.59 J1_PCIE2.61 J1_PCIE2.63 J1_PCIE2.65 J1_PCIE2.67
GND_PCIe_PCIE3: C1_PCIE3.1 C2_PCIE3.1 C3_PCIE3.1
GND_PCIe_PCIE4: C1_PCIE4.1 C2_PCIE4.1 C3_PCIE4.1 J1_PCIE4.1 J1_PCIE4.3 J1_PCIE4.9 J1_PCIE4.15 J1_PCIE4.21 J1_PCIE4.24 J1_PCIE4.27 J1_PCIE4.30 J1_PCIE4.33 J1_PCIE4.34 J1_PCIE4.38 J1_PCIE4.39 J1_PCIE4.42 J1_PCIE4.45 J1_PCIE4.48 J1_PCIE4.51 J1_PCIE4.54 J1_PCIE4.57 J1_PCIE4.59 J1_PCIE4.61 J1_PCIE4.63 J1_PCIE4.65 J1_PCIE4.67
GPIO_ETH_EXPANDER: R715.1 U35_I2C_Expander_13.21 U76.2
GPIO_Exp0_Adress0: R492.1 R493.1 U35_I2C_Expander_11.13 | length 7.2
  L1 w0.254: 491.004,209.461 491.779,209.461 493.186,208.055 494.586,208.055 494.838,208.307 R492.1@494.838,209.018 494.841,209.021 496.081,209.021 496.084,209.024 R493.1@496.834,209.024
GPIO_Exp0_Adress1: R494.1 R495.1 U35_I2C_Expander_11.12 | length 8
  L1 w0.254: U35_I2C_Expander_11.12@491.004,210.111 491.011,210.117 v1(492.63,210.117) ; v1@495.901,210.12 494.842,210.12 R494.1@494.838,210.124 495.901,210.124 v1(495.903,210.122) ; v1@495.902,210.119 496.831,210.119 R495.1@496.833,210.117
  L14 (Sign) w0.254: v1(492.63,210.117) 495.898,210.117 v1(495.903,210.122)
GPIO_Exp0_Adress2: R496.1 R497.1 U35_I2C_Expander_11.11 | length 7.3
  L1 w0.254: 491.004,210.761 491.745,210.761 491.779,210.727 493.388,212.336 494.247,212.336 494.728,211.855 494.728,211.327 R496.1@494.838,211.217 R497.1@496.833,211.217
GPIO_Exp0_Int0: R661.1 U1.AA6 U35_I2C_Expander_11.16
GPIO_Exp0_Int1: R662.1 U1.AA5 U35_I2C_Expander_11.15
GPIO_Exp1_Adress0: R500.1 R501.1 U35_I2C_Expander_12.13 | length 6.7
  L1 w0.254: 473.645,219.05 474.331,219.05 475.481,217.9 477.065,217.9 477.365,218.2 477.365,218.597 R500.1@477.415,218.647 479.302,218.647 R501.1@479.304,218.65
GPIO_Exp1_Adress1: R502.1 R503.1 U35_I2C_Expander_12.12 | length 6.6
  L1 w0.254: U35_I2C_Expander_12.12@473.645,219.7 v1(475.264,219.7) ; R502.1@477.415,219.7 477.448,219.666 v1(478.306,219.666) 478.324,219.684 479.287,219.684 R503.1@479.304,219.702
  L14 (Sign) w0.254: v1(475.264,219.7) 475.297,219.666 v1(478.306,219.666)
GPIO_Exp1_Adress2: R504.1 R505.1 U35_I2C_Expander_12.11 | length 6.8
  L1 w0.254: 473.645,220.35 474.281,220.35 475.481,221.55 477.065,221.55 477.415,221.2 R504.1@477.415,220.747 479.302,220.747 R505.1@479.304,220.75
GPIO_Exp1_Int0: R663.1 U1.AD2 U35_I2C_Expander_12.16
GPIO_Exp1_Int1: R664.1 U1.AE2 U35_I2C_Expander_12.15
GPIO_Exp2_Adress0: R508.1 R509.1 U35_I2C_Expander_13.13 | length 7.3
  L1 w0.254: 491.292,219.05 492.343,219.05 493.537,217.856 495.129,217.856 495.279,218.006 R508.1@495.279,218.656 R509.1@497.372,218.656
GPIO_Exp2_Adress1: R510.1 R511.1 U35_I2C_Expander_13.12 | length 8.5
  L1 w0.254: U35_I2C_Expander_13.12@491.292,219.7 491.308,219.683 v1(493.079,219.683) ; R511.1@497.372,219.7 497.37,219.698 496.481,219.698 v1(496.479,219.695) ; v1(496.479,219.695) 496.475,219.691 495.287,219.691 R510.1@495.279,219.683 495.292,219.695 v1(496.479,219.695)
  L14 (Sign) w0.254: v1(493.079,219.683) 493.092,219.695 v1(496.479,219.695)
GPIO_Exp2_Adress2: R512.1 R513.1 U35_I2C_Expander_13.11 | length 7.2
  L1 w0.254: 491.292,220.35 492.343,220.35 493.543,221.55 494.921,221.55 495.28,221.191 R512.1@495.28,220.7 R513.1@497.372,220.7
GPIO_Exp2_Int0: R688.1 U1.AD1 U35_I2C_Expander_13.16
  other v1: 486.767,217.4 487.867,217.4 488.967,217.4 490.067,217.4 486.767,218.5 487.867,218.5 488.967,218.5 490.067,218.5 486.767,219.6 487.867,219.6 488.967,219.6 490.067,219.6 486.767,220.7 487.867,220.7 488.967,220.7 490.067,220.7
GPIO_Exp2_Int1: R744.1 U1.AE1 U35_I2C_Expander_13.15
GPIO_Exp3_Adress0: R516.1 R517.1 U35_I2C_Expander_14.13 | length 6.3
  L1 w0.254: U35_I2C_Expander_14.13@488.942,240.947 489.527,240.947 490.897,242.317 491.957,242.317 492.306,241.968 492.306,241.562 R516.1@492.377,241.49 R517.1@494.096,241.491
GPIO_Exp3_Adress1: R518.1 R519.1 U35_I2C_Expander_14.12 | length 6
  L1 w0.254: U35_I2C_Expander_14.12@488.942,240.297 488.99,240.345 489.015,240.32 v1(490.444,240.32) ; R518.1@492.377,240.386 v1(493.156,240.386) R519.1@494.096,240.386
  L14 (Sign) w0.254: v1(490.444,240.32) 492.353,240.32 492.377,240.345 ; 492.361,240.386 v1(493.156,240.386)
GPIO_Exp3_Adress2: R520.1 R521.1 U35_I2C_Expander_14.11 | length 6.2
  L1 w0.254: U35_I2C_Expander_14.11@488.942,239.647 489.846,239.647 490.996,238.497 492.106,238.497 492.379,238.769 R520.1@492.379,239.273 R521.1@494.098,239.273
GPIO_Exp3_Int0: R817.1 U1.AC3 U35_I2C_Expander_14.16
GPIO_Exp3_Int1: R818.1 U1.AC2 U35_I2C_Expander_14.15
GPIO_Exp4_Adress0: R524.1 R525.1 U35_I2C_Expander_15.13 | length 6.3
  L1 w0.254: 406.329,233.52 407.257,233.52 407.67,233.107 408.407,232.37 409.572,232.37 409.722,232.52 R524.1@409.722,233.02 ; R524.1@409.572,233.02 R525.1@411.481,233.02
GPIO_Exp4_Adress1: R526.1 R527.1 U35_I2C_Expander_15.12 | length 5.4
  L1 w0.254: U35_I2C_Expander_15.12@406.329,234.17 v1(407.484,234.17) ; v1@410.349,234.17 R527.1@411.481,234.17
  L14 (Sign) w0.254: v1(407.484,234.17) v1(410.562,234.17)
GPIO_Exp4_Adress2: R528.1 R529.1 U35_I2C_Expander_15.11 | length 6
  L1 w0.254: 406.329,234.82 407.257,234.82 407.67,235.233 408.415,235.977 409.574,235.977 409.722,235.829 R528.1@409.722,235.364 ; R528.1@409.847,235.364 R529.1@411.481,235.364
GPIO_Exp4_Int0: R819.1 U1.AA3 U35_I2C_Expander_15.16
GPIO_Exp4_Int1: R820.1 U1.AB3 U35_I2C_Expander_15.15
GPIO_Exp5_Adress0: R697.1 R698.1 U35_I2C_Expander_10.13 | length 6.5
  L1 w0.254: 473.645,229.715 474.631,229.715 475.825,228.521 476.929,228.521 477.129,228.721 R697.1@477.129,229.356 R698.1@478.98,229.356
GPIO_Exp5_Adress1: R699.1 R700.1 U35_I2C_Expander_10.12 | length 6.3
  L1 w0.254: U35_I2C_Expander_10.12@473.645,230.365 473.648,230.362 v1(474.964,230.362) ; R699.1@477.129,230.362 v1(478.11,230.362) R700.1@478.98,230.362
  L14 (Sign) w0.254: v1(474.964,230.362) v1(478.11,230.362)
GPIO_Exp5_Adress2: R701.1 R702.1 U35_I2C_Expander_10.11 | length 6.5
  L1 w0.254: 473.645,231.015 474.629,231.015 475.879,232.265 476.738,232.265 477.129,231.874 R701.1@477.129,231.39 R702.1@478.98,231.39
GPIO_Exp5_Int0: R821.1 U1.AB1 U35_I2C_Expander_10.16
GPIO_Exp5_Int1: R822.1 U1.AC1 U35_I2C_Expander_10.15
GPIO_Exp6_Adress0: R703.1 R704.1 U35_I2C_Expander_16.13 | length 5.8
  L1 w0.254: 489.728,251.489 490.632,251.489 491.475,250.647 492.765,250.647 492.956,250.838 R703.1@492.956,251.174 R704.1@494.769,251.174
GPIO_Exp6_Adress1: R705.1 R706.1 U35_I2C_Expander_16.12 | length 5.9
  L1 w0.254: U35_I2C_Expander_16.12@489.728,252.139 v1(490.925,252.139) ; R705.1@492.956,252.139 v1(493.858,252.139) R706.1@494.769,252.139
  L14 (Sign) w0.254: v1(490.925,252.139) v1(493.858,252.139)
GPIO_Exp6_Adress2: R707.1 R708.1 U35_I2C_Expander_16.11 | length 5.9
  L1 w0.254: 489.728,252.789 490.503,252.789 491.385,253.672 492.807,253.672 492.956,253.523 R707.1@492.956,253.124 R708.1@494.769,253.124
GPIO_Exp6_Int0: R823.1 U1.AA2 U35_I2C_Expander_16.16
GPIO_Exp6_Int1: R824.1 U1.AA1 U35_I2C_Expander_16.15
GPIO_Exp_Reset0: R746.1 U35_I2C_Expander?.21 U35_I2C_Expander_11.14
GPIO_Exp_Reset1: R747.1 U35_I2C_Expander?.20 U35_I2C_Expander_12.14
GPIO_Exp_Reset1.SCL: R559_I2C_Bridge_2.1 U3_I2C_Bridge_2.2 U35_I2C_Expander_10.8 U35_I2C_Expander_11.8 U35_I2C_Expander_12.8 U35_I2C_Expander_13.8
GPIO_Exp_Reset1.SDA: R560_I2C_Bridge_2.1 U3_I2C_Bridge_2.1 U35_I2C_Expander_10.9 U35_I2C_Expander_11.9 U35_I2C_Expander_12.9 U35_I2C_Expander_13.9
GPIO_Exp_Reset2: R748.1 U35_I2C_Expander?.2 U35_I2C_Expander_13.14
GPIO_Exp_Reset3: R749.1 U35_I2C_Expander?.18 U35_I2C_Expander_14.14
GPIO_Exp_Reset4: R750.1 U35_I2C_Expander?.3 U35_I2C_Expander_15.14
GPIO_Exp_Reset5: R751.1 U35_I2C_Expander?.22 U35_I2C_Expander_10.14
GPIO_Exp_Reset6: R752.1 U35_I2C_Expander?.19 U35_I2C_Expander_16.14
Ground: C63.2 C64.2 C67.2 C70.2 C75.2 C76.2 C77.2 C78.1 C79.1 C80.1 C81.2 C82.2 C83.2 C88.2 C89.2 C90.2 C91.2 C92.2 C93.2 C96.2 C99.1 C100.1 C101.1 C102.1 C103.1 C104.1 C105.1 C106.1 C107.1 C108.1 C109.1 C110.1 C124.1 C125.1 C126.1 C127.1 C141.1 C142.1 C143.1 C144.1 C145.1 C146.1 C147.1 C148.1 C162.1 C163.1 C164.1 C165.1 C179.1 C180.1 C572.1 C574.1 C575.1 C576.1 C578.1 C579.1 C590.1 C591.1 C592.1 FB36.2 R437.1 R439.1 R545.1 U16.44 U16.65 U61.3 U61.8 U61.13 U61.18 U61.21 X9.2
  other v1: 233.292,139.105 234.192,139.105 235.092,139.105 233.292,140.005 234.192,140.005 235.092,140.005 233.292,140.905 234.192,140.905 235.092,140.905 327.823,177.914 329.013,177.914 330.203,177.914 331.393,177.914 332.583,177.914 326.603,179.134 327.823,179.134 329.013,179.134 330.203,179.134 331.393,179.134 332.583,179.134 333.803,179.134 326.603,180.324 327.823,180.324 329.013,180.324 330.203,180.324 331.393,180.324 332.583,180.324 333.803,180.324 326.603,181.514 327.823,181.514 329.013,181.514 330.203,181.514 331.393,181.514 332.583,181.514 333.803,181.514 326.603,182.704 327.823,182.704 329.013,182.704 330.203,182.704 331.393,182.704 332.583,182.704 333.803,182.704 326.603,183.894 327.823,183.894 329.013,183.894 330.203,183.894 331.393,183.894 332.583,183.894 333.803,183.894 327.823,185.114 329.013,185.114 330.203,185.114 331.393,185.114 332.583,185.114
Ground_PWR_PoE: C702.1 C703.1 C704.1 D27.2 R159.1 R160.1 R667.1 R670.2 U65.3 U65.8 U65.21 | length 3.7
  L1 w0.254: U65.3@50.492,81.207 U65.21@52.332,81.207 U65.8@52.332,79.367
  other v1: 51.782,80.657 52.882,80.657 51.782,81.757 52.882,81.757
  other v5: 48.16,79.421 48.733,84.301 46.685,84.389 48.733,85.557
HI_Speed_En_PCIE0: U35_I2C_Expander_11.3
HI_Speed_En_PCIE1: U35_I2C_Expander_11.4
HI_Speed_En_PCIE2: U35_I2C_Expander_11.28
HI_Speed_En_PCIE3: U35_I2C_Expander_12.20
HI_Speed_En_PCIE4: U35_I2C_Expander_12.19
HI_Speed_PWR_En: U35_I2C_Expander_11.21
HI_Speed_PWR_En_I2C: U35_I2C_Expander_11.2
HI_Speed_PWR_En_SPI: U35_I2C_Expander_11.18
HI_Speed_PWR_nRST: U35_I2C_Expander_11.20
HW_Conf_05028: R128.1 R129.1 U16.64
I2C0_En: 
I2C0_Reset: 
I2C0Master_SCL: J12.1 R85.1 R774.1 U36_U_Translator_I2C3.3
I2C0Master_SDA: J12.2 R86.1 R775.1 U36_U_Translator_I2C3.4
I2C1_En: U35_I2C_Expander1.19
I2C1_Reset: U35_I2C_Expander1.17
I2C1Master_SCL: J13.1 R83.1 R772.1 U36_U_Translator_I2C2.3
I2C1Master_SDA: J13.2 R84.1 R773.1 U36_U_Translator_I2C2.4
I2C_05028_SCL: R130.2 R132.1 U16.36
I2C_05028_SDA: R131.2 R134.1 U16.35
I2C_SCL_SFP0: J32.5 R559_I2C_Bridge_3.1 U3_I2C_Bridge_3.2
I2C_SCL_SFP1: J33.5 R227_I2C_Bridge_3.1 U3_I2C_Bridge_3.4
I2C_SCL_SFP2: J34.5 R225_I2C_Bridge_3.1 U3_I2C_Bridge_3.6
I2C_SCL_SFP3: J35.5 R223_I2C_Bridge_3.1 U3_I2C_Bridge_3.8
I2C_SDA_SFP0: J32.4 R560_I2C_Bridge_3.1 U3_I2C_Bridge_3.1
I2C_SDA_SFP1: J33.4 R558_I2C_Bridge_3.1 U3_I2C_Bridge_3.3
I2C_SDA_SFP2: J34.4 R226_I2C_Bridge_3.1 U3_I2C_Bridge_3.5
I2C_SDA_SFP3: J35.4 R224_I2C_Bridge_3.1 U3_I2C_Bridge_3.7
I2CFPGA_Master_SCL: R363.2 U1.AG1 U36_U_Translator_I2C1.3 U36_U_Translator_I2C4.3
I2CFPGA_Master_SDA: R364.2 U1.AF3 U36_U_Translator_I2C1.4 U36_U_Translator_I2C4.4
ILIM1: C345.2 R610.1 U34.26 | length 3.2
  L1 w0.254: R610.1@118.546,45.463 118.486,45.403 118.486,44.464 118.427,44.405 U34.26@120.477,44.405
ILIM1_1: C389.2 R619.1 U37.26 | length 2.6
  L1 w0.254: C389.2@208.951,44.41 R619.1@209.916,44.41 209.916,44.36 210.089,44.187 210.139,44.187 210.466,43.859 U37.26@211.295,43.859
ILIM1_2: C430.2 R625.2 U38.26 | length 3
  L1 w0.254: R625.2@162.268,42.063 162.258,42.053 162.258,41.035 163.278,40.015 U38.26@163.783,40.015
ILIM2: C349.2 R611.1 U34.15 | length 3.5
  L1 w0.254: U34.15@124.977,44.406 125.826,44.406 125.833,44.399 126.458,45.025 126.896,45.025 R611.1@127.049,45.178 ; C349.2@127.029,44.139 127.049,44.159 R611.1@127.049,45.178 ; R611.1@127.069,45.198 R611.1@127.049,45.178
ILIM2_1: C393.2 R620.1 U37.15 | length 2.5
  L1 w0.254: U37.15@215.795,43.859 U37.15@215.795,43.859 215.943,43.861 216.491,44.41 R620.1@217.055,44.41 C393.2@218.055,44.409
ILIM2_2: C434.2 R302.2 U38.15 | length 2.6
  L1 w0.254: U38.15@168.283,40.015 168.285,40.017 168.658,40.017 169.281,40.64 C434.2@169.734,40.64 169.734,41.467 R302.2@169.684,41.515 R302.2@169.684,41.515
IMU_INT1: R426.1 R530.2 U1.AD11 U58.4
IMU_INT2: R425.1 R531.2 U1.AD10 U58.9
InSel_05028_00: U16.20
InSel_05028_01: U16.17
InSel_05028_10: U16.28
InSel_05028_11: U16.29
INTA_EXP_MAIN: U1.AE3 U35_I2C_Expander?.16
INTB_EXP_MAIN: U1.Y1 U35_I2C_Expander?.15
Interrupt0: R506.2 U1.AC12 U64_U_Pomiar_pradu_napiecia_3.3
Interrupt1: R507.2 U1.AD12 U64_U_Pomiar_pradu_napiecia_4.3
Interrupt2: R514.2 U1.AA12 U64_U_Pomiar_pradu_napiecia_5.3 | length 1.2
  L1 w0.164: v10(219.703,134.035) 219.703,135.12 U64_U_Pomiar_pradu_napiecia_5.3@219.753,135.17
Interrupt3: R515.2 U1.AA11 U64_U_Pomiar_pradu_napiecia_6.3
Interrupt4: R522.2 U1.AB11 U35_I2C_Expander1.16
Interrupt5: R523.2 U1.AC11 U72.3
Interrupt8: R546.2 U1.AB10 U35_I2C_Expander3.16
Interrupt9: R547.2 U1.AB9 U35_I2C_Expander3.15
Interrupt10: R548.2 U1.Y10
Interrupt11: R549.2 U1.AA10 U35_I2C_Expander1.23 U64_U_Pomiar_pradu_napiecia_1.3
Interrupt12: R550.2 U1.AC9 U35_I2C_Expander1.24 U64_U_Pomiar_pradu_napiecia_2.3
Interrupt13: R551.2 U1.AD9 U35_I2C_Expander1.15
Interrupt14: R552.2 U1.AC6
Interrupt15: R553.2 U1.AD6
Interrupt16: R554.2 U1.W8 U64_U_Pomiar_pradu_napiecia_7.3
Interrupt17: R555.2 U1.Y8 U64_U_Pomiar_pradu_napiecia_8.3
Interrupt18: R556.2 U1.Y7 U64_U_Pomiar_pradu_napiecia_9.3
Interrupt19: R557.2 U1.AA7 U64_U_Pomiar_pradu_napiecia_10.3
Interrupt20: R735.2 U1.AD5 U64_U_Pomiar_pradu_napiecia_11.3
LED_0: R329.1 U39.47
LED_0_RJ: R329.2 T21.17
LED_1: R330.1 U39.46
LED_1_RJ: R330.2 T21.18
LED_2: R331.1 U39.45
LED_2_RJ: R331.2 T21.19
LED_3: R332.2 U39.39
LED_3_RJ: R332.1 T21.20
Logic_Out_KEY: R649.2 T26.3
LTC6952_1_CP_Out: C46.2 R77.2 U12.43 X1.2
LTC6952_1_REF_N: C53.1 R81.2 U12.46
LTC6952_1_REF_P: C54.1 R81.1 U12.45
LTC6952_1_Temp: R607.2 U12.49
LTC6952_1_VCO_N: C334.2 R532.2 U12.38
LTC6952_1_VCO_P: R533.1 U12.37
LTC6952_2_REF_N: C42.2 U13.46
LTC6952_2_REF_P: C41.2 U13.45
LTC6952_2_REF_SMA_N: C42.1 J3.2 R75.1
LTC6952_2_REF_SMA_P: C41.1 J2.2 R75.2
LTC6952_2_Temp: R736.2 U13.49
LTC6952_3_REF_N: C44.2 U14.46
LTC6952_3_REF_P: C43.2 U14.45
LTC6952_3_REF_SMA_N: C44.1 J5.2 R76.1
LTC6952_3_REF_SMA_P: C43.1 J4.2 R76.2
LTC6952_3_Temp: R765.2 U14.49
MIO_0: R768.2 U1.H17
MIO_1: R769.2
MIO_2: R770.2
MIO_3: R771.2 U1.D19
MIO_4: R772.2 U1.J17
MIO_5: R773.2 U1.C19
MIO_6: R774.2 U1.D20
MIO_7: R775.2 U1.E19
MIO_8: R776.2 U1.E20
MIO_9: R777.2 U1.F20
MIO_10: R778.2 U1.F18
MIO_11: R779.2 U1.G18
MIO_12: R780.2 U1.H18
MIO_13: R87.1 U1.G19
MIO_14: R88.1 U1.E18
MIO_15: R89.1 U1.J19
MIO_16: R90.1 U1.K17
MIO_17: R91.1 U1.C18
MIO_18: R92.1 U1.K18
MIO_19: R93.1 U1.K16
MIO_20: R94.1 U1.A20
MIO_21: R95.1 U1.H19
MIO_22: R96.1 U1.F17
MIO_23: R781.2 U1.K19
MIO_24: R782.2 U1.A18
MIO_25: R783.2 U1.B18
MIO_26: R784.2 U1.B20
MIO_27: R785.2 U1.B21
MIO_28: R786.2 U1.A21
MIO_29: R787.2 U1.D21
MIO_30: R788.2 U1.C21
MIO_31: R789.2 U1.A22
MIO_32: R790.2 U1.G20
MIO_33: R791.2 U1.C22
MIO_34: R792.2 U1.B24
MIO_35: R793.2 U1.B23
MIO_36: R794.2 U1.D22
MIO_37: R795.2 U1.F21
MIO_38: R796.2 U1.C23
MIO_39: R101.1 U1.E22
MIO_40: R102.1 U1.C24
MIO_41: R103.1 U1.D24
MIO_42: R104.1 U1.E23
MIO_43: R797.2 U1.F22
MIO_44: R798.2 U1.E24
MIO_45: R799.2 U1.F23
MIO_46: R105.1 U1.K20
MIO_47: R107.1 U1.K21
MIO_48: R108.1 U1.J21
MIO_49: R110.1 U1.G21
MIO_50: R111.1 U1.J20
MIO_51: R112.1 U1.H21
MIO_52: R362.1 U1.A24
MIO_53: R800.2 U1.B25
MIO_54: R115.1 U1.A23
MIO_55: R801.2 U1.B26
MIO_56: R116.1 U1.A25
MIO_57: R117.1 U1.A26
MIO_58: R118.1 U1.A28
MIO_59: R119.1 U1.A27
MIO_60: R120.1 U1.C26
MIO_61: R121.1 U1.B29
MIO_62: R122.1 U1.B28
MIO_63: R802.2 U1.A29
MIO_64: R803.2 U1.B30
MIO_65: R804.2 U1.D25
MIO_66: R805.2 U1.C27
MIO_67: R806.2 U1.C28
MIO_68: R807.2 U1.C29
MIO_69: R808.2 U1.D27
MIO_70: R809.2 U1.D26
MIO_71: R810.2 U1.D30
MIO_72: R811.2 U1.E27
MIO_73: R812.2 U1.E30
MIO_74: R813.2 U1.E29
MIO_75: R814.2 U1.D29
MIO_76: R815.2 U1.E28
MIO_77: R816.2 U1.E25
MIO_GPIO_0_12: J15.2 R780.1
MIO_GPIO_0_23: J16.2 R98.1 R781.1
MIO_GPIO_1_38: J17.2 R796.1
MIO_GPIO_2_66: J19.2 R805.1
MIO_GPIO_2_70: J20.2 R809.1
MIO_GPIO_2_73: J22.2 R812.1
MIO_GPIO_2_74: J23.2 R813.1 U36_U_Translator_I2C2.8
MIO_GPIO_2_75: J24.2 R814.1 U36_U_Translator_I2C3.8
MODE: R669.2 R670.1 U65.2 | length 2.9
  L1 w0.254: R669.2@48.076,81.536 48.076,81.586 48.576,82.086 R670.1@49.059,82.086 49.059,82.036 49.232,81.863 49.282,81.863 49.438,81.707 U65.2@50.492,81.707
NetBT1_2: BT1.2 R650.1 T22.2
NetC36_1: C36.1 R52.2 R54.2
NetC45_2: C45.2 R77.1
NetC78_2: C78.2 U16.7
NetC79_2: C79.2 U16.38
NetC80_2: C80.2 U16.48
NetC91_1: C91.1 U16.39
NetC96_1: C96.1 U16.47
NetC207_2: C207.2 C208.1 J33.15 L3.2
NetC209_2: C209.2 C210.1 J33.20 L4.2
NetC211_2: C211.2 C212.1 J34.15 L5.2
NetC213_2: C213.2 C214.1 J34.20 L6.2
NetC215_2: C215.2 C216.1 J35.15 L7.2
NetC217_2: C217.2 C218.1 J35.20 L8.2
NetC277_2: C277.2
NetC278_2: C278.2
NetC289_2: C289.2
NetC290_2: C290.2
NetC301_2: C301.2
NetC302_2: C302.2
NetC320_1: C320.1 U30.9
NetC321_1: C321.1 U30.10
NetC322_2: C322.2 U30.3 X3.1
NetC323_2: C323.2 U30.2 X3.2
NetC334_1: C334.1 X1.10
NetC335_2: C335.2 R532.1 R533.2
NetC341_1: C341.1 J26.1
NetC351_2: C351.2 R268.2 U34.3 | length 4.2
  L1 w0.254: R268.2@120.402,37.776 120.402,39.054 120.551,39.203 121.325,39.203 C351.2@121.352,39.23 121.352,39.235 121.977,39.86 U34.3@121.977,40.906
NetC356_2: C356.2 R272.2 R277.1 R278.1 U34.2 U34.4 U34.7 U34.9 U34.32 | length 25
  L1 w0.254: R278.1@116.439,42.574 116.579,42.434 116.579,41.843 118.253,40.17 120.588,40.17 v1@120.627,40.209 ; U34.32@120.477,41.406 120.413,41.406 120.411,41.404 120.411,40.426 v1@120.627,40.209 ; U34.2@121.477,40.906 121.477,40.565 121.054,40.142 120.695,40.142 v1@120.627,40.209 ; U34.4@122.477,40.906 122.477,39.778 122.451,39.751 122.451,38.369 122.626,38.194 122.931,38.194 R272.2@122.978,38.24 122.978,38.29 123.251,38.563 123.372,38.563 123.676,38.867 124.134,38.867 124.277,39.01 C356.2@124.277,39.015 124.277,39.673 124.679,40.075 v1(124.679,40.094) 124.679,40.133 124.977,40.432 U34.9@124.977,41.406
  L16 w0.254: v1(120.627,40.17) 120.667,40.17 120.743,40.094 v1(124.679,40.094) 126.443,40.094 v1(128.799,42.449)
NetC357_2: C357.2 U34.13 U34.28 | length 10.4
  L1 w0.254: v1(119.896,43.406) U34.28@120.477,43.406 ; U34.13@124.977,43.406 124.979,43.404 125.128,43.404 125.132,43.399 126.383,43.399 126.881,42.9 126.881,42.667 v1(126.953,42.596)
  L16 w0.254: v1(119.896,43.406) 120.269,43.033 126.516,43.033 v1(126.953,42.596)
NetC471_2: C471.2 T21.12
NetC472_2: C472.2 T21.6
NetC473_2: C473.2 T21.1
NetC474_2: C474.2 T21.7
NetC475_2: C475.2 T21.S1
NetC476_2: C476.2 T21.S2
NetC532_1: C532.1 U44.14
NetC533_1: C533.1 U44.15
NetC534_1: C534.1 U44.16
NetC537_1: C537.1 FB26.2
NetC537_4: C537.4 FB27.2
NetC537_Z1: C537.Z1 FB28.1
NetC549_2: C549.2 R687.1 | length 1.1
  L1 w0.254: C549.2@160.268,37.01 160.271,37.013 161.326,37.013 R687.1@161.328,37.015
NetC558_Z1: C558.Z1 C558.Z2 C672.2
NetC568_2: C568.2 FB33.1 R433.2 U60.10 U60.11 U60.12 U60.13 U60.14
NetC571_1: C571.1 U60.7 | length 1.1
  L1 w0.254: U60.7@290.365,197.356 290.365,197.206 290.59,196.981 C571.1@290.59,196.303
NetC573_1: C573.1 R436.1 R437.2 U61.16 | length 4.2
  L1 w0.254: R436.1@231.886,135.975 232.331,135.975 232.48,136.124 232.48,136.153 232.713,136.385 232.834,136.385 233.007,136.558 R437.2@233.007,136.608 ; C573.1@231.92,136.949 231.92,136.939 232.251,136.608 R437.2@233.007,136.608 ; U61.16@233.192,138.03 233.192,137.745 233.007,137.561 R437.2@233.007,136.608
NetC577_1: C577.1 R438.1 R439.2 U61.10 | length 3.8
  L1 w0.254: R438.1@230.837,142.714 230.837,142.764 231.445,143.372 C577.1@232.192,143.372 232.808,143.372 232.981,143.199 R439.2@232.981,143.172 232.981,142.476 233.192,142.265 U61.10@233.192,141.98
NetC578_2: C578.2 U61.7 | length 1.3
  L1 w0.254: C578.2@234.68,143.268 234.686,143.262 234.686,141.986 U61.7@234.692,141.98
NetC579_2: C579.2 U61.19 | length 1.3
  L1 w0.254: C579.2@234.692,136.764 U61.19@234.692,138.03
NetC581_2: C581.2 C582.2 C583.2 FB34.2 R442.2 U62.1 U62.2 U62.3
NetC584_2: C584.2 R445.2 U62.7 | length 2.2
  L1 w0.254: U62.7@423.755,341.342 425.308,341.342 C584.2@425.358,341.292 C584.2@425.781,340.869
NetC588_1: C588.1 R543.2
NetC588_2: C588.2 C589.1 R545.2
NetC591_2: C591.2 C592.2 FB37.2 X9.4
NetC597_2: C597.2 R140.1 U65.17 | length 4.4
  L1 w0.254: U65.17@52.832,83.047 52.855,83.07 52.855,83.685 54.121,84.951 C597.2@55.15,84.951 55.138,84.939 55.138,84.038 R140.1@55.125,84.026 R140.1@55.116,84.035
NetC603_1: C603.1 R113.1 R114.2 U19.20
NetC604_1: C604.1 U19.25 | length 4.4
  L1 w0.254: U19.25@243.224,251.458 243.226,251.46 243.226,251.928 243.727,252.428 244.352,252.428 244.749,252.825 244.749,253.571 245.366,254.188 245.366,254.373 245.509,254.516 C604.1@245.514,254.516
NetC605_1: C605.1 R212.1 R214.2 U19.21
NetC612_1: C612.1 R216.2 R218.2 U19.22
NetC616_1: C616.1 R220.1 R274.2 U19.19
NetC633_2: C633.2 R613.1 | length 2.3
  L1 w0.254: R613.1@110.833,68.85 C633.2@110.833,71.136
NetC634_2: C634.2 R615.2 U34.11 U34.30 | length 14.8
  L1 w0.254: v1(119.401,42.381) 119.424,42.404 120.475,42.404 U34.30@120.477,42.406 ; U34.11@124.977,42.406 124.979,42.404 125.128,42.404 125.132,42.399 125.627,42.399 126.423,41.603 v1(126.423,39.14)
  L16 w0.254: v1(119.401,42.381) 119.401,40.619 120.411,39.609 121.982,39.609 122.114,39.476 122.114,39.385 122.387,39.112 C634.2@122.392,39.112 122.407,39.126 123.363,39.126 R615.2@123.378,39.14 v1(126.423,39.14)
NetC635_2: C635.2 R615.1 | length 1
  L16 w0.254: C635.2@122.392,38.147 122.439,38.194 123.331,38.194 R615.1@123.378,38.24
NetC636_2: C636.2 R616.1 | length 2.2
  L1 w0.254: R616.1@134.085,68.801 C636.2@134.085,71.026
NetC637_2: C637.2 R288.1
NetC638_2: C638.2 R298.1
NetC643_2: C643.2 R623.1 | length 1.1
  L1 w0.254: R623.1@218.105,40.305 C643.2@219.162,40.305
NetC644_2: C644.2 R624.1 | length 1
  L1 w0.254: C644.2@207.935,40.359 R624.1@208.901,40.359
NetC645_2: C645.2 R306.1
NetC646_2: C646.2 R316.1
NetC652_2: C652.2 R631.1 | length 1
  L1 w0.254: R631.1@170.674,37 170.679,37.005 171.661,37.005 C652.2@171.666,37.01
NetC655_1: C655.1 U49.6 | length 1.2
  L1 w0.254: U49.6@185.559,132.309 185.589,132.34 186.691,132.34 C655.1@186.721,132.37
NetC656_1: C656.1 U50.6 | length 1.7
  L1 w0.254: U50.6@185.559,127.46 186.791,127.46 186.968,127.283 186.973,127.283 187.116,127.14 C656.1@187.116,127.135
